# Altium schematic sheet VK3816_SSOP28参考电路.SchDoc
size A4
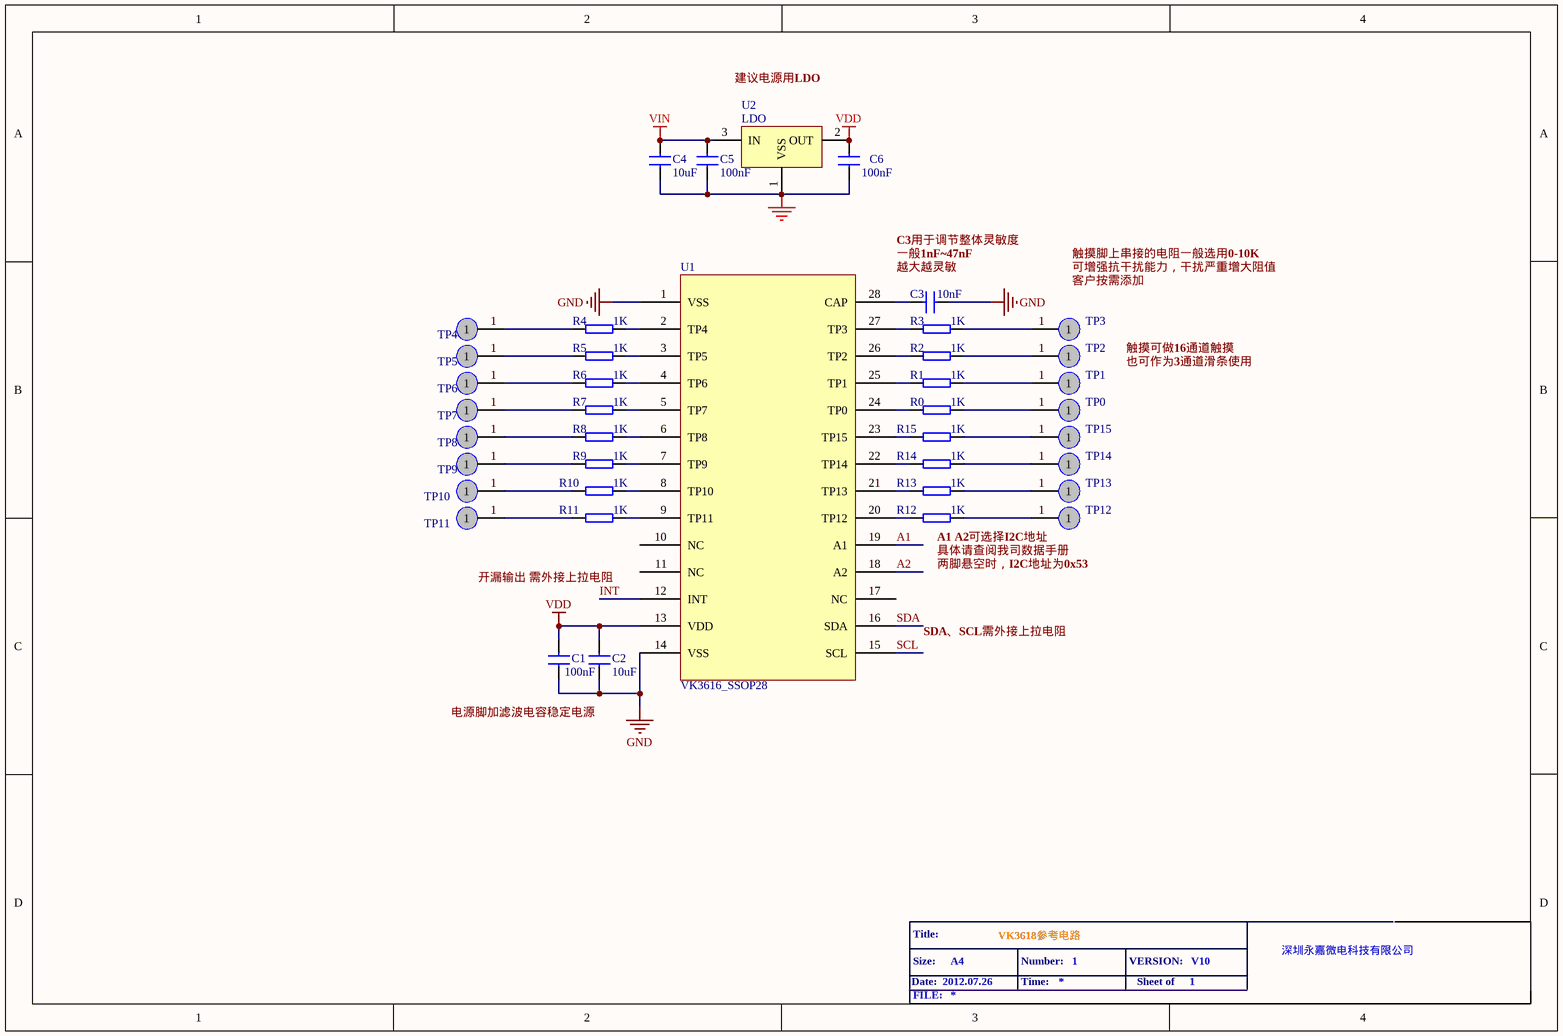
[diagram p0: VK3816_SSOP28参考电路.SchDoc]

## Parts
C1  100nF  [0603-C]
C2  10uF  [0603-C]
C3  value 10nF  [0603-C]  (hidden comment: 10uF)
C4  10uF  [0805-C]
C5  100nF  [0805-C]
C6  100nF  [0805-C]
R0  1K  [0603-R]
R1  1K  [0603-R]
R2  1K  [0603-R]
R3  1K  [0603-R]
R4  1K  [0603-R]
R5  1K  [0603-R]
R6  1K  [0603-R]
R7  1K  [0603-R]
R8  1K  [0603-R]
R9  1K  [0603-R]
R10  1K  [0603-R]
R11  1K  [0603-R]
R12  1K  [0603-R]
R13  1K  [0603-R]
R14  1K  [0603-R]
R15  1K  [0603-R]
TP0  TPAD  [TP-PAD0]  (value not drawn)
TP1  TPAD  [TP-PAD0]  (value not drawn)
TP2  TPAD  [TP-PAD0]  (value not drawn)
TP3  TPAD  [TP-PAD0]  (value not drawn)
TP4  TPAD  [TP-PAD0]  (value not drawn)
TP5  TPAD  [TP-PAD0]  (value not drawn)
TP6  TPAD  [TP-PAD0]  (value not drawn)
TP7  TPAD  [TP-PAD0]  (value not drawn)
TP8  TPAD  [TP-PAD0]  (value not drawn)
TP9  TPAD  [TP-PAD0]  (value not drawn)
TP10  TPAD  [TP-PAD0]  (value not drawn)
TP11  TPAD  [TP-PAD0]  (value not drawn)
TP12  TPAD  [TP-PAD0]  (value not drawn)
TP13  TPAD  [TP-PAD0]  (value not drawn)
TP14  TPAD  [TP-PAD0]  (value not drawn)
TP15  TPAD  [TP-PAD0]  (value not drawn)
U1  VK3616_SSOP28
U2  LDO  [SOT-23]

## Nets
GND: C1.2 C2.2 C3.1 C4.2 C5.2 C6.2 U1.1(VSS) U1.14(VSS) U2.1(VSS)
VDD: C1.1 C2.1 C6.1 U1.13(VDD) U2.2(OUT)
VIN: C4.1 C5.1 U2.3(IN)
A1: U1.19(A1)
A2: U1.18(A2)
INT: U1.12(INT)
SCL: U1.15(SCL)
SDA: U1.16(SDA)
NetC3_2: C3.2 U1.28(CAP)
NetR0_1: R0.1 U1.24(TP0)
NetR0_2: R0.2 TP0.1
NetR1_1: R1.1 U1.25(TP1)
NetR1_2: R1.2 TP1.1
NetR2_1: R2.1 U1.26(TP2)
NetR2_2: R2.2 TP2.1
NetR3_1: R3.1 U1.27(TP3)
NetR3_2: R3.2 TP3.1
NetR4_1: R4.1 U1.2(TP4)
NetR4_2: R4.2 TP4.1
NetR5_1: R5.1 U1.3(TP5)
NetR5_2: R5.2 TP5.1
NetR6_1: R6.1 U1.4(TP6)
NetR6_2: R6.2 TP6.1
NetR7_1: R7.1 U1.5(TP7)
NetR7_2: R7.2 TP7.1
NetR8_1: R8.1 U1.6(TP8)
NetR8_2: R8.2 TP8.1
NetR9_1: R9.1 TP9.1
NetR9_2: R9.2 U1.7(TP9)
NetR10_1: R10.1 TP10.1
NetR10_2: R10.2 U1.8(TP10)
NetR11_1: R11.1 TP11.1
NetR11_2: R11.2 U1.9(TP11)
NetR12_1: R12.1 U1.20(TP12)
NetR12_2: R12.2 TP12.1
NetR13_1: R13.1 U1.21(TP13)
NetR13_2: R13.2 TP13.1
NetR14_1: R14.1 U1.22(TP14)
NetR14_2: R14.2 TP14.1
NetR15_1: R15.1 U1.23(TP15)
NetR15_2: R15.2 TP15.1

Not connected (* = marked no-connect by the designer): U1 10(NC) 11(NC) 17(NC)

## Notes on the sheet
- 建议电源用LDO
- C3用于调节整体灵敏度
- 一般1nF~47nF
- (near C3) 越大越灵敏
- 触摸脚上串接的电阻一般选用0-10K
- 可增强抗干扰能力，干扰严重增大阻值
- (near TP3) 客户按需添加
- 触摸可做16通道触摸
- 也可作为3通道滑条使用
- 开漏输出 需外接上拉电阻
- (near R12) A1 A2可选择I2C地址
- 两脚悬空时，I2C地址为0x53
- (near R12) 具体请查阅我司数据手册
- SDA、SCL需外接上拉电阻
- (near C1) 电源脚加滤波电容稳定电源
- Date:
- Title:
- Size:
- 2012.07.26
- A4
- VK3618参考电路
- Number:
- Time:
- 1
- VERSION:
- Sheet of
- V10
- 深圳永嘉微电科技有限公司
- FILE:

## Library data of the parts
C1-C6 = CAP: Capacitor
R0-R15 = RES: Resistor
TP0-TP15 = TPAD: TESTING
U2 = V6206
